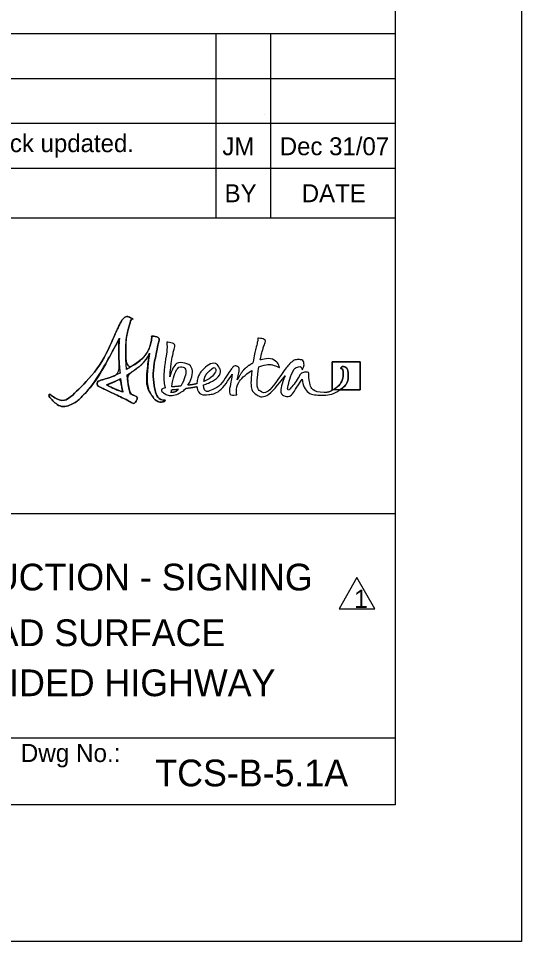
# Model space of a CAD drawing. Extents: x 1342 to 1558, y 178 to 457.
# Drawn here: x 1518.5 to 1558.3, y 177.9 to 251 of the extents above; entities that cross this region are included whole.
import ezdxf

# ---------------------------------------------------------------- set-up
doc = ezdxf.new("R2010")
doc.units = 0
doc.layers.add('Level 53', color=7, linetype='Continuous')
doc.layers.add('Level 60', color=7, linetype='Continuous')

msp = doc.modelspace()

# ---------------------------------------------------------------- linework, layer by layer
at = {"layer": 'Level 53'}
msp.add_line((1543.914, 221.573), (1543.364, 221.573), dxfattribs=at)
msp.add_lwpolyline([(1543.914, 221.573), (1545.53, 221.573), (1545.53, 223.804), (1543.3, 223.804), (1543.3, 221.573), (1543.364, 221.573)], dxfattribs=at)
for points, degree in [([(1529.929, 220.764), (1529.69, 220.8), (1529.375, 221.126), (1529.28, 221.663), (1529.109, 222.629), (1529.21, 223.583), (1529.494, 225.004), (1529.548, 225.273), (1529.732, 225.739), (1529.148, 225.829), (1528.963, 225.857), (1529.059, 225.766), (1529.007, 225.52), (1528.782, 224.461), (1527.917, 223.699), (1527.048, 223.188), (1526.957, 224.399), (1526.994, 225.745), (1527.222, 226.57), (1527.414, 227.266), (1527.643, 227.138), (1527.359, 227.285), (1527.061, 227.439), (1526.74, 227.235), (1526.48, 226.717), (1526.22, 226.198), (1525.023, 223.382), (1523.112, 221.482), (1522.134, 220.509), (1521.249, 221.01), (1521.072, 221.159), (1520.928, 221.281), (1520.875, 221.093), (1521.053, 220.901), (1521.845, 220.048), (1523, 220.537), (1523.421, 220.958), (1524.584, 222.12), (1525.936, 224.622), (1526.483, 225.684), (1526.432, 225.086), (1526.416, 224.083), (1526.527, 222.909), (1525.935, 222.62), (1525.404, 222.451), (1525.154, 222.385), (1524.883, 222.314), (1524.715, 222.203), (1524.71, 222.078), (1524.705, 221.94), (1524.887, 221.824), (1525.15, 221.699), (1525.619, 221.477), (1526.99, 220.829), (1527.328, 220.632), (1527.618, 220.464), (1527.759, 220.596), (1527.845, 220.777), (1527.957, 221.013), (1527.65, 221.149), (1527.352, 221.238), (1527.238, 221.636), (1527.146, 222.172), (1527.085, 222.762), (1527.783, 223.191), (1528.47, 223.763), (1528.865, 224.477), (1528.766, 223.88), (1528.51, 221.849), (1529.151, 220.991), (1529.292, 220.802), (1529.604, 220.595), (1529.908, 220.626), (1530.051, 220.64), (1530.124, 220.734), (1530.11, 220.764), (1530.095, 220.793), (1530.013, 220.752), (1529.929, 220.764)], 3), ([(1527.048, 223.188), (1526.957, 224.399), (1526.994, 225.745), (1527.222, 226.57), (1527.414, 227.266), (1527.643, 227.138), (1527.359, 227.285), (1527.061, 227.439), (1526.74, 227.235), (1526.48, 226.717), (1526.22, 226.198), (1525.023, 223.382), (1523.112, 221.482), (1522.134, 220.509), (1521.249, 221.01), (1521.072, 221.159), (1520.928, 221.281), (1520.875, 221.093), (1521.053, 220.901), (1521.845, 220.048), (1523, 220.537), (1523.421, 220.958), (1524.584, 222.12), (1525.936, 224.622), (1526.483, 225.684)], 3), ([(1529.929, 220.764), (1529.69, 220.8), (1529.375, 221.126), (1529.28, 221.663), (1529.109, 222.629), (1529.21, 223.583), (1529.494, 225.004), (1529.548, 225.273), (1529.732, 225.739), (1529.148, 225.829), (1528.963, 225.857), (1529.059, 225.766), (1529.007, 225.52), (1528.782, 224.461), (1527.917, 223.699), (1527.048, 223.188)], 3), ([(1526.483, 225.684), (1526.432, 225.086), (1526.416, 224.083), (1526.527, 222.909)], 2), ([(1530.466, 222.606), (1530.512, 223.174), (1530.603, 223.867), (1530.731, 224.51), (1530.785, 224.779), (1530.969, 225.244), (1530.385, 225.334), (1530.2, 225.363), (1530.228, 225.276), (1530.244, 225.025), (1530.265, 224.688), (1529.892, 222.649), (1530.086, 221.753)], 3), ([(1537.62, 223.947), (1537.685, 224.244), (1537.76, 224.546), (1537.843, 224.84), (1537.918, 225.109), (1538.139, 225.575), (1537.562, 225.664), (1537.379, 225.693), (1537.457, 225.604), (1537.396, 225.356), (1537.285, 224.898), (1537.144, 224.306), (1537.043, 223.71)], 3), ([(1527.085, 222.762), (1527.783, 223.191), (1528.47, 223.763), (1528.865, 224.477)], 2), ([(1528.865, 224.477), (1528.766, 223.88), (1528.51, 221.849), (1529.151, 220.991), (1529.292, 220.802), (1529.604, 220.595), (1529.908, 220.626), (1530.051, 220.64), (1530.124, 220.734), (1530.11, 220.764), (1530.095, 220.793), (1530.013, 220.752), (1529.929, 220.764)], 3), ([(1531.904, 221.944), (1532.318, 222.617), (1532.283, 223.527), (1531.676, 223.68), (1530.972, 223.858), (1530.616, 223.174), (1530.466, 222.606)], 3), ([(1533.13, 221.967), (1533.226, 221.996), (1533.312, 222.027), (1533.385, 222.059), (1534.268, 222.451), (1534.571, 223.041), (1534.347, 223.4), (1534.134, 223.741), (1533.525, 223.638), (1533.044, 223.131), (1532.807, 222.882), (1532.625, 222.453), (1532.604, 222.063)], 3), ([(1537.043, 223.71), (1536.569, 223.437), (1536.128, 222.981), (1535.804, 222.381)], 2), ([(1542.675, 221.375), (1541.759, 221.375), (1541.523, 222.087), (1541.479, 222.439), (1541.45, 222.673), (1541.5, 223.012), (1541.096, 222.967), (1540.813, 222.935), (1540.557, 222.384), (1540.198, 221.92), (1539.89, 221.521), (1539.752, 221.559), (1539.824, 221.902), (1539.913, 222.33), (1540.27, 223.335), (1540.68, 223.409), (1540.869, 223.442), (1540.936, 223.11), (1541.023, 223.318), (1541.111, 223.526), (1541.031, 223.976), (1540.607, 223.976), (1540.311, 223.976), (1539.955, 223.662), (1539.663, 223.304), (1539.409, 222.992), (1538.124, 221.1), (1537.585, 221.508), (1537.333, 221.699), (1537.353, 222.477), (1537.512, 223.393)], 3), ([(1537.512, 223.393), (1538.151, 223.639), (1538.683, 223.559), (1538.984, 223.414), (1539.133, 223.343), (1539.153, 223.353), (1539.09, 223.517), (1538.996, 223.757), (1538.482, 224.132), (1537.678, 223.96), (1537.659, 223.956), (1537.639, 223.951), (1537.62, 223.947)], 3), ([(1543.3, 223.804), (1543.3, 223.804), (1543.3, 221.573), (1543.3, 221.573), (1543.3, 221.573), (1543.364, 221.573), (1543.364, 221.573), (1543.848, 221.863), (1544.174, 222.417), (1544.173, 222.873), (1544.173, 223.267), (1543.964, 223.247), (1543.988, 223.302), (1544.055, 223.46), (1544.548, 223.37), (1544.577, 222.814), (1544.601, 222.342), (1544.354, 221.886), (1543.914, 221.573), (1543.914, 221.573), (1545.53, 221.573), (1545.53, 221.573), (1545.53, 221.573), (1545.53, 223.804), (1545.53, 223.804), (1545.53, 223.804), (1543.3, 223.804), (1543.3, 223.804)], 3), ([(1526.527, 222.909), (1525.935, 222.62), (1525.404, 222.451), (1525.154, 222.385), (1524.883, 222.314), (1524.715, 222.203), (1524.71, 222.078), (1524.705, 221.94), (1524.887, 221.824), (1525.15, 221.699), (1525.619, 221.477), (1526.99, 220.829), (1527.328, 220.632), (1527.618, 220.464), (1527.759, 220.596), (1527.845, 220.777), (1527.957, 221.013), (1527.65, 221.149), (1527.352, 221.238)], 3), ([(1530.616, 221.815), (1530.711, 222.531), (1531.083, 223.526), (1531.547, 223.366), (1531.814, 223.274), (1531.674, 222.435), (1531.331, 221.878)], 3), ([(1532.61, 221.842), (1532.659, 221.449), (1532.915, 221.148), (1533.51, 221.203), (1534.357, 221.282), (1535.108, 222.322), (1535.392, 222.823)], 3), ([(1535.804, 222.381), (1535.86, 222.658), (1535.947, 222.964), (1535.953, 223.17), (1535.959, 223.388), (1535.81, 223.436), (1535.752, 223.453), (1535.626, 223.489), (1535.473, 223.426), (1535.322, 223.213), (1534.969, 222.716), (1534.522, 221.929), (1533.843, 221.598), (1533.356, 221.362), (1533.142, 221.6), (1533.13, 221.967)], 3), ([(1533.602, 223.086), (1533.898, 223.361), (1534.045, 223.341), (1534.084, 223.267), (1534.168, 223.108), (1533.819, 222.545), (1533.152, 222.237)], 3), ([(1533.152, 222.237), (1533.21, 222.54), (1533.369, 222.87), (1533.602, 223.086)], 2), ([(1535.392, 222.823), (1535.341, 222.286), (1534.991, 221.113), (1535.587, 221.173), (1535.821, 221.197), (1535.719, 221.234), (1535.734, 221.436), (1535.785, 222.142), (1536.373, 222.741), (1536.955, 223.108)], 3), ([(1536.955, 223.108), (1536.854, 222.243), (1536.889, 221.47), (1537.282, 221.225), (1538.004, 220.773), (1539.026, 221.962), (1539.589, 222.689)], 3), ([(1543.364, 221.573), (1543.848, 221.863), (1544.174, 222.417), (1544.173, 222.873), (1544.173, 223.267), (1543.964, 223.247), (1543.988, 223.302), (1544.055, 223.46), (1544.548, 223.37), (1544.577, 222.814), (1544.601, 222.342), (1544.354, 221.886), (1543.914, 221.573)], 3), ([(1525.457, 221.976), (1525.766, 222.089), (1526.159, 222.254), (1526.573, 222.471)], 2), ([(1525.457, 221.976), (1525.766, 222.089), (1526.159, 222.254), (1526.573, 222.471), (1526.629, 221.998), (1526.69, 221.655), (1526.757, 221.402), (1526.454, 221.512), (1526.022, 221.688), (1525.457, 221.976)], 3), ([(1526.573, 222.471), (1526.629, 221.998), (1526.69, 221.655), (1526.757, 221.402)], 2), ([(1527.352, 221.238), (1527.238, 221.636), (1527.146, 222.172), (1527.085, 222.762)], 2), ([(1539.589, 222.689), (1539.302, 222.044), (1539.14, 221.216), (1539.571, 221.09), (1540.075, 220.943), (1540.473, 221.78), (1540.939, 222.421)], 3), ([(1540.939, 222.421), (1540.993, 221.961), (1541.3, 221.168), (1542.537, 221.168), (1543.093, 221.168), (1543.565, 221.325), (1543.914, 221.573)], 3), ([(1526.757, 221.402), (1526.454, 221.512), (1526.022, 221.688), (1525.457, 221.976)], 2), ([(1530.086, 221.753), (1529.835, 221.672), (1529.733, 221.483), (1530.056, 221.284), (1530.279, 221.146), (1530.769, 221.101), (1531.264, 221.345), (1531.441, 221.432), (1531.595, 221.555), (1531.723, 221.7)], 3), ([(1530.541, 221.383), (1530.573, 221.41), (1530.593, 221.45), (1530.593, 221.498), (1530.593, 221.529), (1530.594, 221.561), (1530.595, 221.593)], 3), ([(1530.743, 221.384), (1530.661, 221.372), (1530.594, 221.373), (1530.541, 221.383)], 2), ([(1530.595, 221.593), (1530.721, 221.599), (1530.918, 221.613), (1531.152, 221.636)], 2), ([(1531.331, 221.878), (1531.106, 221.855), (1530.868, 221.834), (1530.616, 221.815)], 2), ([(1531.152, 221.636), (1531.029, 221.501), (1530.891, 221.407), (1530.743, 221.384)], 2), ([(1531.723, 221.7), (1532.018, 221.738), (1532.328, 221.785), (1532.61, 221.842)], 2), ([(1532.604, 222.063), (1532.4, 222.018), (1532.165, 221.979), (1531.904, 221.944)], 2), ([(1543.364, 221.573), (1543.159, 221.451), (1542.925, 221.375), (1542.675, 221.375)], 2)]:
    msp.add_open_spline(points, degree=degree, dxfattribs=at)
at = {"layer": 'Level 60'}
for p, q in [((1548.312, 249.746), (1484.432, 249.746)), ((1534.118, 249.746), (1534.118, 235.196)), ((1538.429, 249.746), (1538.429, 235.196)), ((1548.312, 246.197), (1484.432, 246.197)), ((1534.095, 246.191), (1534.095, 235.196)), ((1537.933, 243.333), (1537.933, 243.333)), ((1548.312, 242.648), (1484.432, 242.648)), ((1548.312, 239.1), (1484.432, 239.1)), ((1484.439, 235.196), (1548.282, 235.196)), ((1484.439, 235.196), (1548.312, 235.196)), ((1518.505, 235.196), (1518.505, 235.196)), ((1484.439, 211.787), (1548.282, 211.787)), ((1484.439, 194.053), (1548.282, 194.053)), ((1548.282, 188.732), (1548.282, 188.732)), ((1548.282, 188.732), (1548.282, 188.732)), ((1548.282, 188.732), (1548.282, 188.732)), ((1558.282, 177.923), (1558.282, 177.923))]:
    msp.add_line(p, q, dxfattribs=at)
for points in [[(1342.282, 456.923), (1558.282, 456.923), (1558.282, 177.923), (1342.282, 177.923)], [(1361.408, 446.114), (1548.282, 446.114), (1548.282, 188.732), (1361.408, 188.732)], [(1545.269, 206.727), (1543.85, 204.257), (1546.688, 204.257)]]:
    msp.add_lwpolyline(points, close=True, dxfattribs=at)

# ---------------------------------------------------------------- texts
for s, height, p in [('Note added and Title Block updated.', 1.419, (1496.933, 240.394)), ('TCS-B-5.1A', 2.115, (1529.322, 190.206))]:
    msp.add_text(s, height=height, dxfattribs=at).set_placement(p)
for s, height, rotation, p in [('JM', 1.4189, 360, (1534.622, 240.149)), ('Dec 31/07', 1.419, 360, (1539.163, 240.149)), ('BY', 1.4195, 360, (1534.8, 236.431)), ('DATE', 1.4194, 360, (1540.902, 236.431)), ('UTILITIES CONSTRUCTION - SIGNING', 2.115, 359.99999, (1490.542, 205.707)), ('1', 1.448, 360, (1545.042, 204.314)), ('WORK OFF ROAD SURFACE', 2.115, 359.99999, (1496.353, 201.3)), ('TWO LANE UNDIVIDED HIGHWAY', 2.11517, 359.99999, (1493.403, 197.34)), ('Dwg No.:', 1.4329, 360, (1518.681, 192.131))]:
    msp.add_text(s, height=height, rotation=rotation, dxfattribs=at).set_placement(p)

doc.saveas('drawing.dxf')
